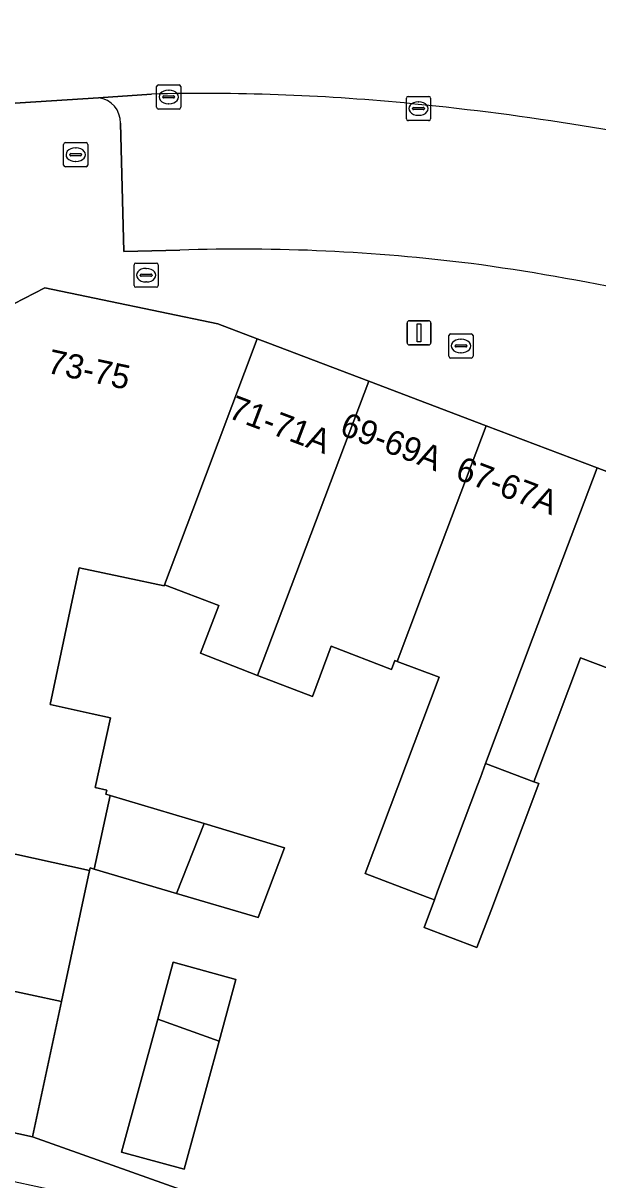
# Model space of a CAD drawing. Extents: x 160856 to 161310, y 384024 to 384878.
# Drawn here: x 161168.6 to 161192.34, y 384804.18 to 384851.95 of the extents above; entities that cross this region are included whole.
import ezdxf

# ---------------------------------------------------------------- set-up
doc = ezdxf.new("R2010")
doc.units = 0
for name, color, linetype in [('IMGEO_Brandkraan', 7, 'Continuous'), ('IMGEO_Erf', 7, 'Continuous'), ('IMGEO_Kolk', 7, 'Continuous'), ('IMGEO_Lichtmast', 7, 'Continuous'), ('IMGEO_Pand', 7, 'Continuous'), ('IMGEO_Pand_nummerreeks', 7, 'Continuous'), ('IMGEO_Parkeervlak_open', 7, 'Continuous'), ('IMGEO_Rijbaan_lokaal_gesloten', 7, 'Continuous'), ('IMGEO_Rioolput', 7, 'Continuous'), ('IMGEO_Voetpad_open', 7, 'Continuous')]:
    doc.layers.add(name, color=color, linetype=linetype)

msp = doc.modelspace()

# ---------------------------------------------------------------- linework, layer by layer
at = {"layer": 'IMGEO_Brandkraan'}
for p, q in [((161173.184, 384841.112), (161173.184, 384841.964)), ((161173.259, 384842.038), (161174.111, 384842.038)), ((161173.672, 384841.818), (161173.697, 384841.818)), ((161174.185, 384841.964), (161174.185, 384841.112)), ((161173.443, 384841.532), (161173.443, 384841.544)), ((161173.881, 384841.495), (161173.483, 384841.495)), ((161173.486, 384841.581), (161173.884, 384841.581)), ((161173.695, 384841.258), (161173.67, 384841.258)), ((161173.927, 384841.544), (161173.927, 384841.532)), ((161174.111, 384841.038), (161173.259, 384841.038))]:
    msp.add_line(p, q, dxfattribs=at)
for points in [[(161173.184, 384841.112), (161173.184, 384841.964)], [(161173.259, 384842.038), (161174.111, 384842.038)], [(161174.185, 384841.964), (161174.185, 384841.112)], [(161174.111, 384841.038), (161173.259, 384841.038)]]:
    msp.add_lwpolyline(points, dxfattribs=at)
for centre, radius, start, end in [((161173.261, 384841.962), 0.0765, 91.552, 178.448), ((161173.261, 384841.962), 0.0765, 91.552, 178.448), ((161174.109, 384841.962), 0.0765, 1.552, 88.448), ((161174.109, 384841.962), 0.0765, 1.552, 88.448), ((161173.483, 384841.541), 0.0403, 85.8775, 175.7526), ((161173.48, 384841.531), 0.0366, 178.938, 274.7102), ((161173.884, 384841.538), 0.043, 264.8664, 352.4533), ((161173.888, 384841.543), 0.0386, 1.7309, 96.639), ((161173.261, 384841.114), 0.0765, 181.552, 268.448), ((161173.261, 384841.114), 0.0765, 181.552, 268.448), ((161174.109, 384841.114), 0.0765, 271.552, 358.448), ((161174.109, 384841.114), 0.0765, 271.552, 358.448)]:
    msp.add_arc(centre, radius, start, end, dxfattribs=at)
for centre, major_axis, ratio, start_param, end_param in [((161173.671, 384841.538), (-0.387, 0.002), 0.722429, 4.712389, 7.853982), ((161173.696, 384841.538), (-0.39, 0.002), 0.717154, 1.570796, 4.712389)]:
    msp.add_ellipse(centre, major_axis=major_axis, ratio=ratio, start_param=start_param, end_param=end_param, dxfattribs=at)
at = {"layer": 'IMGEO_Erf'}
msp.add_lwpolyline([(161194.21, 384824.76), (161191.623, 384825.737), (161189.692, 384820.621), (161189.899, 384820.543), (161187.911, 384815.276), (161187.345, 384813.778), (161185.158, 384814.604), (161185.588, 384815.749), (161185.295, 384815.86), (161182.726, 384816.829), (161185.79, 384824.944), (161184.045, 384825.59), (161183.958, 384825.622), (161183.82, 384825.255), (161181.33, 384826.219), (161180.553, 384824.134), (161178.287, 384825.012), (161175.931, 384825.924), (161176.686, 384827.902), (161174.436, 384828.749), (161174.422, 384828.71), (161172.87, 384829.037), (161170.917, 384829.449), (161170.574, 384827.84), (161169.715, 384823.812), (161171.448, 384823.43), (161172.208, 384823.263), (161171.572, 384820.377), (161172.056, 384820.271), (161172.021, 384820.105), (161172.203, 384820.051), (161176.077, 384818.889), (161179.398, 384817.894), (161178.31, 384815.012), (161174.937, 384816.008), (161171.533, 384817.012), (161171.368, 384817.061), (161171.345, 384816.953), (161170.186, 384811.544), (161168.987, 384805.951), (161180.675, 384801.797)], dxfattribs=at)
msp.add_lwpolyline([(161175.254, 384804.623), (161172.668, 384805.328), (161174.166, 384810.822), (161174.804, 384813.163), (161177.391, 384812.457), (161176.694, 384809.902)], close=True, dxfattribs=at)
at = {"layer": 'IMGEO_Kolk'}
for p, q in [((161174.191, 384849.399), (161175.043, 384849.399)), ((161174.116, 384848.473), (161174.116, 384849.325)), ((161174.375, 384848.893), (161174.375, 384848.905)), ((161174.418, 384848.942), (161174.816, 384848.942)), ((161174.604, 384849.179), (161174.629, 384849.179)), ((161174.859, 384848.905), (161174.859, 384848.893)), ((161175.117, 384849.325), (161175.117, 384848.473)), ((161184.504, 384848.92), (161185.356, 384848.92)), ((161175.043, 384848.399), (161174.191, 384848.399)), ((161174.813, 384848.856), (161174.415, 384848.856)), ((161174.627, 384848.619), (161174.602, 384848.619)), ((161184.429, 384847.994), (161184.429, 384848.846)), ((161184.688, 384848.414), (161184.688, 384848.426)), ((161184.731, 384848.463), (161185.129, 384848.463)), ((161184.917, 384848.7), (161184.942, 384848.7)), ((161185.172, 384848.426), (161185.172, 384848.414)), ((161185.43, 384848.846), (161185.43, 384847.994)), ((161185.126, 384848.377), (161184.728, 384848.377)), ((161184.94, 384848.14), (161184.915, 384848.14)), ((161185.356, 384847.92), (161184.504, 384847.92)), ((161186.183, 384838.192), (161186.183, 384839.044)), ((161186.258, 384839.118), (161187.11, 384839.118)), ((161186.671, 384838.898), (161186.696, 384838.898)), ((161187.184, 384839.044), (161187.184, 384838.192)), ((161186.442, 384838.612), (161186.442, 384838.624)), ((161186.88, 384838.575), (161186.482, 384838.575)), ((161186.485, 384838.661), (161186.883, 384838.661)), ((161186.926, 384838.624), (161186.926, 384838.612)), ((161187.11, 384838.118), (161186.258, 384838.118)), ((161186.694, 384838.338), (161186.669, 384838.338))]:
    msp.add_line(p, q, dxfattribs=at)
for points in [[(161174.191, 384849.399), (161175.043, 384849.399)], [(161174.116, 384848.473), (161174.116, 384849.325)], [(161175.117, 384849.325), (161175.117, 384848.473)], [(161184.504, 384848.92), (161185.356, 384848.92)], [(161175.043, 384848.399), (161174.191, 384848.399)], [(161184.429, 384847.994), (161184.429, 384848.846)], [(161185.43, 384848.846), (161185.43, 384847.994)], [(161185.356, 384847.92), (161184.504, 384847.92)], [(161186.183, 384838.192), (161186.183, 384839.044)], [(161186.258, 384839.118), (161187.11, 384839.118)], [(161187.184, 384839.044), (161187.184, 384838.192)], [(161187.11, 384838.118), (161186.258, 384838.118)]]:
    msp.add_lwpolyline(points, dxfattribs=at)
for centre, radius, start, end in [((161174.193, 384849.323), 0.0765, 91.552, 178.448), ((161174.193, 384849.323), 0.0765, 91.552, 178.448), ((161175.041, 384849.323), 0.0765, 1.552, 88.448), ((161175.041, 384849.323), 0.0765, 1.552, 88.448), ((161174.415, 384848.902), 0.0403, 85.8775, 175.7526), ((161174.412, 384848.892), 0.0366, 178.938, 274.7102), ((161174.816, 384848.899), 0.043, 264.8664, 352.4533), ((161174.82, 384848.904), 0.0386, 1.7309, 96.639), ((161184.506, 384848.844), 0.0765, 91.552, 178.448), ((161184.506, 384848.844), 0.0765, 91.552, 178.448), ((161185.354, 384848.844), 0.0765, 1.552, 88.448), ((161185.354, 384848.844), 0.0765, 1.552, 88.448), ((161174.193, 384848.475), 0.0765, 181.552, 268.448), ((161174.193, 384848.475), 0.0765, 181.552, 268.448), ((161175.041, 384848.475), 0.0765, 271.552, 358.448), ((161175.041, 384848.475), 0.0765, 271.552, 358.448), ((161184.728, 384848.423), 0.0403, 85.8775, 175.7526), ((161184.725, 384848.413), 0.0366, 178.938, 274.7102), ((161185.129, 384848.42), 0.043, 264.8664, 352.4533), ((161185.133, 384848.425), 0.0386, 1.7309, 96.639), ((161184.506, 384847.996), 0.0765, 181.552, 268.448), ((161184.506, 384847.996), 0.0765, 181.552, 268.448), ((161185.354, 384847.996), 0.0765, 271.552, 358.448), ((161185.354, 384847.996), 0.0765, 271.552, 358.448), ((161186.26, 384839.042), 0.0765, 91.552, 178.448), ((161186.26, 384839.042), 0.0765, 91.552, 178.448), ((161187.108, 384839.042), 0.0765, 1.552, 88.448), ((161187.108, 384839.042), 0.0765, 1.552, 88.448), ((161186.482, 384838.621), 0.0403, 85.8775, 175.7526), ((161186.479, 384838.611), 0.0366, 178.938, 274.7102), ((161186.883, 384838.618), 0.043, 264.8664, 352.4533), ((161186.887, 384838.623), 0.0386, 1.7309, 96.639), ((161186.26, 384838.194), 0.0765, 181.552, 268.448), ((161186.26, 384838.194), 0.0765, 181.552, 268.448), ((161187.108, 384838.194), 0.0765, 271.552, 358.448), ((161187.108, 384838.194), 0.0765, 271.552, 358.448)]:
    msp.add_arc(centre, radius, start, end, dxfattribs=at)
for centre, major_axis, ratio, start_param, end_param in [((161174.603, 384848.899), (-0.387, 0.002), 0.722429, 4.712389, 7.853982), ((161174.628, 384848.899), (-0.39, 0.002), 0.717154, 1.570796, 4.712389), ((161184.916, 384848.42), (-0.387, 0.002), 0.722429, 4.712389, 7.853982), ((161184.941, 384848.42), (-0.39, 0.002), 0.717154, 1.570796, 4.712389), ((161186.67, 384838.618), (-0.387, 0.002), 0.722429, 4.712389, 7.853982), ((161186.695, 384838.618), (-0.39, 0.002), 0.717154, 1.570796, 4.712389)]:
    msp.add_ellipse(centre, major_axis=major_axis, ratio=ratio, start_param=start_param, end_param=end_param, dxfattribs=at)
at = {"layer": 'IMGEO_Lichtmast'}
for p, q in [((161184.456, 384838.757), (161184.456, 384839.557)), ((161184.456, 384839.557), (161184.456, 384838.757)), ((161184.556, 384839.657), (161185.346, 384839.657)), ((161185.346, 384839.657), (161184.556, 384839.657)), ((161185.446, 384839.557), (161185.446, 384838.757)), ((161185.446, 384838.757), (161185.446, 384839.557)), ((161185.346, 384838.657), (161184.556, 384838.657)), ((161184.556, 384838.657), (161185.346, 384838.657))]:
    msp.add_line(p, q, dxfattribs=at)
msp.add_lwpolyline([(161184.876, 384839.532), (161185.026, 384839.532), (161185.026, 384838.782), (161184.876, 384838.782), (161184.876, 384839.532)], dxfattribs=at)
for centre, start, end in [((161184.556, 384839.557), 90, 180), ((161184.556, 384839.557), 90, 180), ((161185.346, 384839.557), 0, 90), ((161185.346, 384839.557), 360, 90), ((161184.556, 384838.757), 180, 270), ((161184.556, 384838.757), 180, 270), ((161185.346, 384838.757), 270, 0), ((161185.346, 384838.757), 270, 0)]:
    msp.add_arc(centre, 0.1, start, end, dxfattribs=at)
at = {"layer": 'IMGEO_Pand'}
for points in [[(161172.208, 384823.263), (161171.448, 384823.43), (161169.715, 384823.812), (161170.574, 384827.84), (161170.917, 384829.449), (161172.87, 384829.037), (161174.422, 384828.71), (161174.436, 384828.749), (161175.609, 384831.855), (161178.275, 384838.914), (161176.648, 384839.532), (161169.502, 384841.015), (161168.221, 384840.36), (161163.699, 384818.637), (161171.345, 384816.953), (161171.368, 384817.061), (161171.533, 384817.012), (161172.203, 384820.051), (161172.021, 384820.105), (161172.056, 384820.271), (161171.572, 384820.377)], [(161182.877, 384837.164), (161178.703, 384838.751), (161178.275, 384838.914), (161175.609, 384831.855), (161174.436, 384828.749), (161176.686, 384827.902), (161175.931, 384825.924), (161178.287, 384825.012)], [(161187.721, 384835.323), (161182.877, 384837.164), (161178.287, 384825.012), (161180.553, 384824.134), (161181.33, 384826.219), (161183.82, 384825.255), (161183.958, 384825.622), (161184.045, 384825.59), (161185.05, 384828.251)], [(161192.304, 384833.582), (161187.721, 384835.323), (161185.05, 384828.251), (161184.045, 384825.59), (161185.79, 384824.944), (161182.726, 384816.829), (161185.295, 384815.86), (161185.588, 384815.749), (161185.721, 384816.102), (161187.363, 384820.472), (161187.486, 384820.799), (161187.702, 384821.373), (161189.665, 384826.598)], [(161196.885, 384831.84), (161192.304, 384833.582), (161189.665, 384826.598), (161187.702, 384821.373), (161189.692, 384820.621), (161191.623, 384825.737), (161194.21, 384824.76), (161194.25, 384824.866)], [(161189.692, 384820.621), (161187.702, 384821.373), (161187.486, 384820.799), (161187.363, 384820.472), (161185.721, 384816.102), (161185.588, 384815.749), (161185.158, 384814.604), (161187.345, 384813.778), (161187.911, 384815.276), (161189.899, 384820.543)], [(161172.203, 384820.051), (161171.533, 384817.012), (161174.937, 384816.008), (161176.077, 384818.889)], [(161174.937, 384816.008), (161178.31, 384815.012), (161179.398, 384817.894), (161176.077, 384818.889)], [(161171.345, 384816.953), (161163.699, 384818.637), (161163.69, 384818.639), (161162.491, 384813.194), (161170.186, 384811.544)], [(161162.491, 384813.194), (161161.27, 384807.651), (161166.153, 384806.575), (161168.987, 384805.951), (161170.186, 384811.544)], [(161174.166, 384810.822), (161176.694, 384809.902), (161177.391, 384812.457), (161174.804, 384813.163)], [(161174.166, 384810.822), (161172.668, 384805.328), (161175.254, 384804.623), (161176.694, 384809.902)]]:
    msp.add_lwpolyline(points, close=True, dxfattribs=at)
at = {"layer": 'IMGEO_Parkeervlak_open'}
for points in [[(161173.909, 384849.019), (161171.718, 384848.858)], [(161172.62, 384847.815), (161172.756, 384842.522), (161175.074, 384842.576)]]:
    msp.add_lwpolyline(points, dxfattribs=at)
for centre, radius, start, end in [((161175.997, 384760.46), 88.584, 84.59669, 91.3509), ((161171.612, 384847.855), 1.008, 357.7163, 83.991), ((161173.271, 384732.867), 116.311, 77.67003, 84.53946), ((161177.565, 384766.103), 76.513, 82.84055, 91.86573), ((161174.564, 384749.53), 93.336, 77.97292, 82.28078)]:
    msp.add_arc(centre, radius, start, end, dxfattribs=at)
at = {"layer": 'IMGEO_Rijbaan_lokaal_gesloten'}
msp.add_lwpolyline([(161166.204, 384852.749), (161163.31, 384852.581), (161163.539, 384848.326), (161165.449, 384848.458), (161171.718, 384848.858), (161173.909, 384849.019)], dxfattribs=at)
for centre, radius, start, end in [((161175.997, 384760.46), 88.584, 84.59669, 91.3509), ((161173.271, 384732.867), 116.311, 77.67003, 84.53946)]:
    msp.add_arc(centre, radius, start, end, dxfattribs=at)
at = {"layer": 'IMGEO_Rioolput'}
for p, q in [((161170.35, 384847.015), (161171.202, 384847.015)), ((161170.275, 384846.089), (161170.275, 384846.941)), ((161170.534, 384846.509), (161170.534, 384846.521)), ((161170.577, 384846.558), (161170.975, 384846.558)), ((161170.763, 384846.795), (161170.788, 384846.795)), ((161171.018, 384846.521), (161171.018, 384846.509)), ((161171.276, 384846.941), (161171.276, 384846.089)), ((161171.202, 384846.015), (161170.35, 384846.015)), ((161170.972, 384846.472), (161170.574, 384846.472)), ((161170.786, 384846.235), (161170.761, 384846.235))]:
    msp.add_line(p, q, dxfattribs=at)
for points in [[(161170.35, 384847.015), (161171.202, 384847.015)], [(161170.275, 384846.089), (161170.275, 384846.941)], [(161171.276, 384846.941), (161171.276, 384846.089)], [(161171.202, 384846.015), (161170.35, 384846.015)]]:
    msp.add_lwpolyline(points, dxfattribs=at)
for centre, radius, start, end in [((161170.352, 384846.939), 0.0765, 91.552, 178.448), ((161170.352, 384846.939), 0.0765, 91.552, 178.448), ((161171.2, 384846.939), 0.0765, 1.552, 88.448), ((161171.2, 384846.939), 0.0765, 1.552, 88.448), ((161170.574, 384846.518), 0.0403, 85.8775, 175.7526), ((161170.571, 384846.508), 0.0366, 178.938, 274.7102), ((161170.975, 384846.515), 0.043, 264.8664, 352.4533), ((161170.979, 384846.52), 0.0386, 1.7309, 96.639), ((161170.352, 384846.091), 0.0765, 181.552, 268.448), ((161170.352, 384846.091), 0.0765, 181.552, 268.448), ((161171.2, 384846.091), 0.0765, 271.552, 358.448), ((161171.2, 384846.091), 0.0765, 271.552, 358.448)]:
    msp.add_arc(centre, radius, start, end, dxfattribs=at)
for centre, major_axis, ratio, start_param, end_param in [((161170.762, 384846.515), (-0.387, 0.002), 0.722429, 4.712389, 7.853982), ((161170.787, 384846.515), (-0.39, 0.002), 0.717154, 1.570796, 4.712389)]:
    msp.add_ellipse(centre, major_axis=major_axis, ratio=ratio, start_param=start_param, end_param=end_param, dxfattribs=at)
at = {"layer": 'IMGEO_Voetpad_open'}
for points in [[(161171.718, 384848.858), (161165.449, 384848.458), (161163.539, 384848.326), (161162.359, 384848.232)], [(161175.074, 384842.576), (161172.756, 384842.522), (161172.62, 384847.815)], [(161155.329, 384843.038), (161160.189, 384841.869), (161165.016, 384840.827), (161168.221, 384840.36), (161169.502, 384841.015), (161176.648, 384839.532), (161178.275, 384838.914), (161178.703, 384838.751), (161182.877, 384837.164), (161187.721, 384835.323), (161192.304, 384833.582), (161196.885, 384831.84), (161201.466, 384830.099), (161206.047, 384828.358), (161210.628, 384826.617), (161215.35, 384824.822), (161216.116, 384824.531), (161220.078, 384834.88), (161222.199, 384840.723)]]:
    msp.add_lwpolyline(points, dxfattribs=at)
msp.add_lwpolyline([(161168.987, 384805.951), (161166.153, 384806.575), (161161.27, 384807.651), (161160.902, 384805.678), (161165.791, 384804.629), (161169.637, 384803.803), (161187.436, 384796.887), (161187.468, 384796.967), (161192.798, 384794.861), (161193.567, 384796.922), (161183.464, 384800.779), (161183.272, 384800.258), (161180.486, 384801.28), (161180.675, 384801.797)], close=True, dxfattribs=at)
for centre, radius, start, end in [((161171.612, 384847.855), 1.008, 357.7163, 83.991), ((161177.565, 384766.103), 76.513, 82.84055, 91.86573), ((161174.564, 384749.53), 93.336, 77.97292, 82.28078)]:
    msp.add_arc(centre, radius, start, end, dxfattribs=at)

# ---------------------------------------------------------------- texts
at = {"layer": 'IMGEO_Pand_nummerreeks'}
for s, rotation, p in [('73-75', 347.9908, (161169.551, 384837.515)), ('71-71A', 339.3162, (161177.025, 384835.665)), ('69-69A', 338.9896, (161181.628, 384834.975)), ('67-67A', 339.2016, (161186.398, 384833.151))]:
    msp.add_text(s, height=1, rotation=rotation, dxfattribs=at).set_placement(p)

doc.saveas('drawing.dxf')
